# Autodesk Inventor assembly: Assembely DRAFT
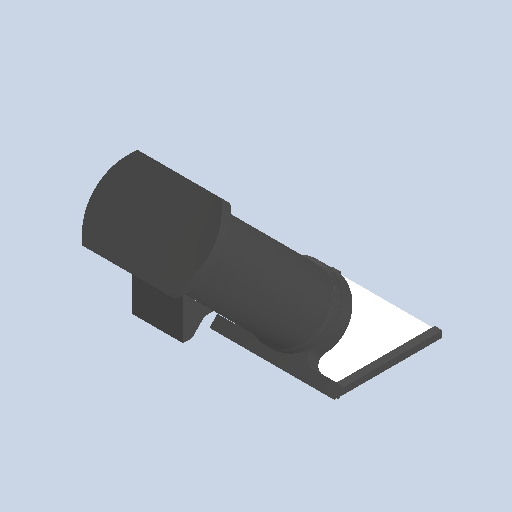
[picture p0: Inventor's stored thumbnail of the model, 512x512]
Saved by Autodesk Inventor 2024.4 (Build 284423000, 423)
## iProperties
Created: 2025-04
Part Number: Assembely DRAFT
Document SubType Name: Assembly
Designer: AdminForWorker
Title: Assembely DRAFT v7
Author: AdminForWorker
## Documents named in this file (9)
- c:\worker\convert-fusion-r02-cosv3\tmp\job-1\12\temp\files\1718eded-1d8f-43a0-9465-10b5a2cd5079\fe7da212-c289-4978-a3c1-0256e1880308.iam
- c:\worker\convert-fusion-r02-cosv3\tmp\job-1\12\temp\files\1718eded-1d8f-43a0-9465-10b5a2cd5079\HUD screen v1 v2.ipt
- c:\worker\convert-fusion-r02-cosv3\tmp\job-1\12\temp\files\1718eded-1d8f-43a0-9465-10b5a2cd5079\HUD COVER v3.iam
- c:\worker\convert-fusion-r02-cosv3\tmp\job-1\12\temp\files\1718eded-1d8f-43a0-9465-10b5a2cd5079\left bracket v1.ipt
- c:\worker\convert-fusion-r02-cosv3\tmp\job-1\12\temp\files\1718eded-1d8f-43a0-9465-10b5a2cd5079\imu platform (1) v1.ipt
- c:\worker\convert-fusion-r02-cosv3\tmp\job-1\12\temp\files\1718eded-1d8f-43a0-9465-10b5a2cd5079\right bracket v1.ipt
- c:\worker\convert-fusion-r02-cosv3\tmp\job-1\12\temp\files\1718eded-1d8f-43a0-9465-10b5a2cd5079\ring v1.ipt
- c:\worker\convert-fusion-r02-cosv3\tmp\job-1\12\temp\files\1718eded-1d8f-43a0-9465-10b5a2cd5079\aGlass screen v3.ipt
- c:\worker\convert-fusion-r02-cosv3\tmp\job-1\12\temp\files\1718eded-1d8f-43a0-9465-10b5a2cd5079\glass lens v2.ipt
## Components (8 placed, 8 different names)
1. HUD screen v1 v2:1
2. HUD COVER v3:1 [sub-assembly]
3. left bracket v1:1
4. imu platform (1) v1:1
5. right bracket v1:1
6. ring v1:1
7. aGlass screen v3:1
8. glass lens v2:1
